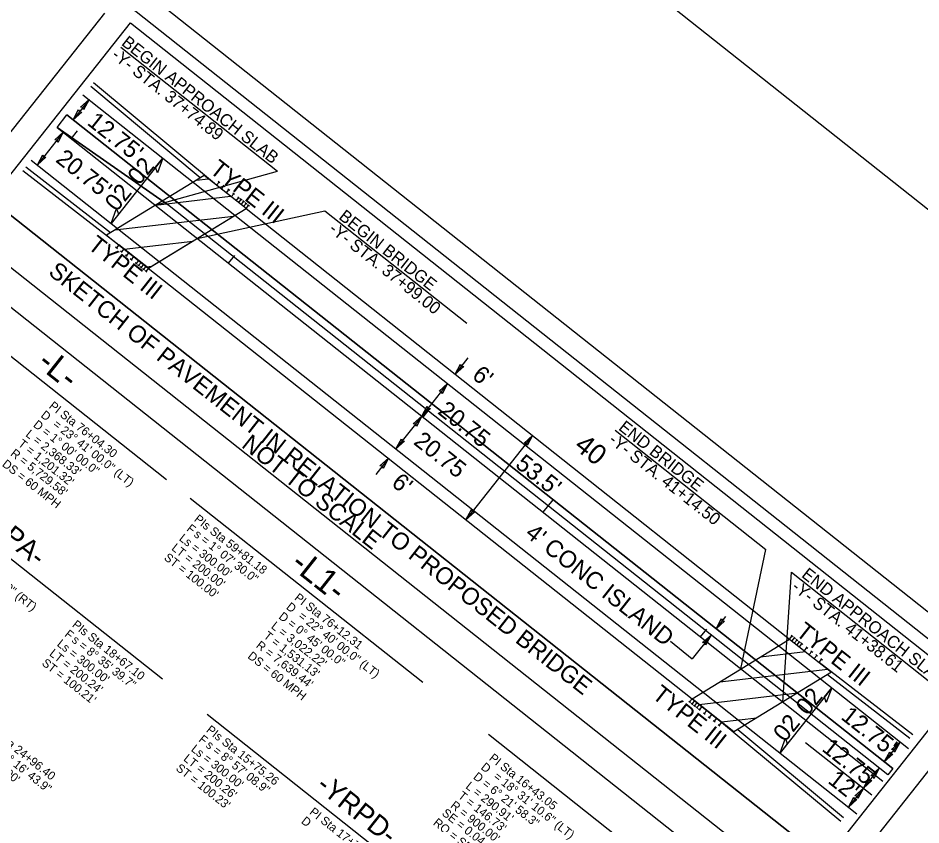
# Model space of a CAD drawing. Extents: x 1771636 to 1784627, y 798645 to 819978.
# Drawn here: x 1783314 to 1784052, y 812522 to 813181 of the extents above; entities that cross this region are included whole.
import ezdxf

# ---------------------------------------------------------------- set-up
doc = ezdxf.new("R2010")
doc.units = 0
for name, color, linetype in [('Exist Building', 7, 'Continuous'), ('Exist Hydro Pool or Reservoir', 7, 'Continuous'), ('Exist Hydro Stream Flow Arrow CELL', 7, 'Continuous'), ('Exist Hydro Stream or Body of Water', 7, 'Continuous'), ('Exist Other Culture Sign CELL', 7, 'Continuous'), ('Exist Other Culture Well CELL', 7, 'Continuous'), ('Exist Roads Change in Surface', 7, 'Continuous'), ('Exist Roads EOP Other', 7, 'Continuous'), ('Exist Roads EOT', 7, 'Continuous'), ('Exist Structure Minor Catch Basin', 7, 'Continuous'), ('Exist Structure Minor Culvert Topo', 7, 'Continuous'), ('Exist Structure Minor Drop Inlet', 7, 'Continuous'), ('Exist Structure Minor Footbridge', 7, 'Continuous'), ('Exist Structure Minor Paved Ditch or Gutter', 7, 'Continuous'), ('Exist Utilities Power Joint Use Telephone CELL', 7, 'Continuous'), ('Exist Utilities Sanitary Sewer Manhole CELL', 7, 'Continuous'), ('Exist Utilities Telephone Pole CELL', 7, 'Continuous'), ('Exist Utilities TV Satellite Dish CELL', 7, 'Continuous'), ('Exist Utilities Water Fire Hydrant CELL', 7, 'Continuous'), ('Exist Vegetation Hedge Row', 7, 'Continuous'), ('Exist Vegetation Shrub CELL', 7, 'Continuous'), ('Exist Vegetation Woods Line', 7, 'Continuous'), ('Prop CMT Guardrail Graphics', 7, 'Continuous')]:
    doc.layers.add(name, color=color, linetype=linetype)

msp = doc.modelspace()

# ---------------------------------------------------------------- linework, layer by layer
at = {"layer": 'Exist Building'}
msp.add_lwpolyline([(1783345.88, 813092.01), (1783354.04, 813102.32), (1784029, 812567.95), (1784024.92, 812562.81), (1783436.11, 813028.98)], close=True, dxfattribs=at)
at = {"layer": 'Exist Hydro Pool or Reservoir'}
for points in [[(1783365.12, 813108.46), (1783372.09, 813114.7), (1783367.62, 813106.41), (1783367.06, 813108.36)], [(1783366.08, 813104.56), (1783359.11, 813098.31), (1783363.58, 813106.6), (1783364.14, 813104.66)], [(1783343.99, 813081.78), (1783350.97, 813088.02), (1783346.49, 813079.73), (1783345.94, 813081.67)], [(1783336.81, 813067.59), (1783329.84, 813061.34), (1783334.31, 813069.63), (1783334.87, 813067.69)], [(1783678.31, 812896.58), (1783671.34, 812890.34), (1783675.81, 812898.63), (1783676.36, 812896.68)], [(1783658.26, 812876.37), (1783665.23, 812882.62), (1783660.76, 812874.33), (1783660.2, 812876.27)], [(1783651.08, 812862.19), (1783644.11, 812855.94), (1783648.58, 812864.23), (1783649.13, 812862.29)], [(1783637.13, 812849.69), (1783644.11, 812855.94), (1783639.63, 812847.65), (1783639.08, 812849.59)], [(1783629.96, 812835.51), (1783622.98, 812829.26), (1783627.46, 812837.55), (1783628.01, 812835.61)], [(1783727.7, 812833.94), (1783734.67, 812840.19), (1783730.2, 812831.9), (1783729.65, 812833.84)], [(1783609.9, 812815.3), (1783616.88, 812821.54), (1783612.4, 812813.25), (1783611.85, 812815.2)], [(1783687.18, 812777.65), (1783680.21, 812771.4), (1783684.68, 812779.69), (1783685.24, 812777.75)], [(1783891.59, 812688.5), (1783884.62, 812682.26), (1783889.09, 812690.55), (1783889.65, 812688.61)], [(1783873.58, 812670.87), (1783880.55, 812677.11), (1783876.07, 812668.82), (1783875.52, 812670.77)], [(1784028.13, 812583.54), (1784035.11, 812589.79), (1784030.63, 812581.49), (1784030.08, 812583.44)], [(1784029.1, 812579.64), (1784022.13, 812573.39), (1784026.6, 812581.68), (1784027.15, 812579.74)], [(1784011.08, 812562), (1784018.05, 812568.25), (1784013.58, 812559.96), (1784013.03, 812561.9)], [(1784012.05, 812558.1), (1784005.07, 812551.85), (1784009.55, 812560.15), (1784010.1, 812558.2)], [(1783998.1, 812545.61), (1784005.07, 812551.85), (1784000.6, 812543.56), (1784000.05, 812545.51)], [(1783999.83, 812542.67), (1783992.86, 812536.42), (1783997.33, 812544.72), (1783997.89, 812542.77)]]:
    msp.add_lwpolyline(points, close=True, dxfattribs=at)
at = {"layer": 'Exist Hydro Stream Flow Arrow CELL'}
msp.add_lwpolyline([(1784297.88, 812505.92), (1781710.58, 814554.31), (1780665.28, 813234), (1783252.58, 811185.61)], close=True, dxfattribs=at)
at = {"layer": 'Exist Other Culture Sign CELL'}
for p, q in [((1783372.09, 813114.7), (1783359.11, 813098.31)), ((1783350.97, 813088.02), (1783329.84, 813061.34)), ((1783681.84, 812903.6), (1783671.34, 812890.34)), ((1783665.23, 812882.62), (1783644.11, 812855.94)), ((1783644.11, 812855.94), (1783622.98, 812829.26)), ((1783734.67, 812840.19), (1783680.21, 812771.4)), ((1783616.88, 812821.54), (1783606.49, 812808.43)), ((1783892.47, 812692.17), (1783884.62, 812682.26)), ((1783880.55, 812677.11), (1783865.23, 812657.77)), ((1783847.29, 812671.98), (1783865.23, 812657.77)), ((1784035.11, 812589.79), (1784022.13, 812573.39)), ((1784018.05, 812568.25), (1784005.07, 812551.85)), ((1784005.07, 812551.85), (1783992.86, 812536.42))]:
    msp.add_line(p, q, dxfattribs=at)
at = {"layer": 'Exist Other Culture Well CELL'}
msp.add_lwpolyline([(1784457.99, 812708.16), (1781817.38, 814798.76), (1780451.82, 813073.93), (1783092.43, 810983.33)], close=True, dxfattribs=at)
at = {"layer": 'Exist Roads Change in Surface'}
for p, q in [((1783476.28, 813044.76), (1783375.76, 813128.45)), ((1783318.06, 813056.79), (1783396.5, 812996.02)), ((1784045.4, 812595.48), (1783968.9, 812654.75)), ((1783889.12, 812606), (1783986.49, 812524.94))]:
    msp.add_line(p, q, dxfattribs=at)
at = {"layer": 'Exist Roads EOP Other'}
for p, q in [((1783367.02, 813118.71), (1784041.98, 812584.35)), ((1783324.78, 813065.35), (1783999.73, 812530.99))]:
    msp.add_line(p, q, dxfattribs=at)
at = {"layer": 'Exist Roads EOT'}
for p, q in [((1783476.28, 813044.76), (1783478.32, 813047.34)), ((1783500.39, 813025.68), (1783476.28, 813044.76)), ((1783479.05, 813046.75), (1783477.58, 813047.92)), ((1783480.3, 813041.58), (1783482.33, 813044.15)), ((1783483.07, 813043.57), (1783481.6, 813044.74)), ((1783484.32, 813038.4), (1783486.35, 813040.97)), ((1783487.09, 813040.39), (1783485.62, 813041.56)), ((1783488.34, 813035.22), (1783490.37, 813037.79)), ((1783491.11, 813037.21), (1783489.63, 813038.38)), ((1783492.35, 813032.04), (1783494.39, 813034.61)), ((1783495.13, 813034.03), (1783493.65, 813035.19)), ((1783494.36, 813030.45), (1783496.4, 813033.02)), ((1783497.13, 813032.44), (1783495.66, 813033.6)), ((1783496.37, 813028.86), (1783498.41, 813031.43)), ((1783499.14, 813030.85), (1783497.67, 813032.01)), ((1783498.38, 813027.27), (1783500.42, 813029.84)), ((1783501.15, 813029.26), (1783499.68, 813030.42)), ((1783500.39, 813025.68), (1783502.43, 813028.25)), ((1783503.16, 813027.67), (1783501.69, 813028.83)), ((1783395.2, 812992.86), (1783393.73, 812994.03)), ((1783396.5, 812996.02), (1783394.46, 812993.45)), ((1783420.61, 812976.93), (1783396.5, 812996.02)), ((1783400.52, 812992.84), (1783398.48, 812990.27)), ((1783399.22, 812989.68), (1783397.75, 812990.85)), ((1783403.24, 812986.5), (1783401.76, 812987.67)), ((1783404.54, 812989.66), (1783402.5, 812987.08)), ((1783407.25, 812983.32), (1783405.78, 812984.49)), ((1783408.55, 812986.47), (1783406.52, 812983.9)), ((1783411.27, 812980.14), (1783409.8, 812981.3)), ((1783412.57, 812983.29), (1783410.54, 812980.72)), ((1783413.28, 812978.55), (1783411.81, 812979.71)), ((1783414.58, 812981.7), (1783412.55, 812979.13)), ((1783415.29, 812976.96), (1783413.82, 812978.12)), ((1783416.59, 812980.11), (1783414.55, 812977.54)), ((1783417.3, 812975.37), (1783415.83, 812976.53)), ((1783418.6, 812978.52), (1783416.56, 812975.95)), ((1783420.61, 812976.93), (1783418.57, 812974.36)), ((1783419.31, 812973.78), (1783417.84, 812974.94)), ((1783944.79, 812673.84), (1783946.83, 812676.41)), ((1783944.79, 812673.84), (1783968.9, 812654.75)), ((1783946.09, 812676.99), (1783947.57, 812675.83)), ((1783946.8, 812672.25), (1783948.84, 812674.82)), ((1783948.1, 812675.4), (1783949.57, 812674.24)), ((1783950.11, 812673.81), (1783951.58, 812672.64)), ((1783948.81, 812670.66), (1783950.85, 812673.23)), ((1783950.82, 812669.07), (1783952.86, 812671.64)), ((1783952.12, 812672.22), (1783953.59, 812671.05)), ((1783952.83, 812667.48), (1783954.87, 812670.05)), ((1783954.13, 812670.63), (1783955.6, 812669.46)), ((1783956.85, 812664.29), (1783958.88, 812666.87)), ((1783958.15, 812667.45), (1783959.62, 812666.28)), ((1783960.87, 812661.11), (1783962.9, 812663.68)), ((1783962.17, 812664.27), (1783963.64, 812663.1)), ((1783964.88, 812657.93), (1783966.92, 812660.5)), ((1783966.18, 812661.09), (1783967.66, 812659.92)), ((1783968.9, 812654.75), (1783970.94, 812657.32)), ((1783970.2, 812657.9), (1783971.67, 812656.74)), ((1783862.24, 812623.1), (1783863.71, 812621.94)), ((1783865.01, 812625.09), (1783862.98, 812622.52)), ((1783867.02, 812623.5), (1783864.99, 812620.93)), ((1783865.01, 812625.09), (1783889.12, 812606)), ((1783869.03, 812621.91), (1783866.99, 812619.34)), ((1783864.25, 812621.51), (1783865.72, 812620.35)), ((1783866.26, 812619.92), (1783867.73, 812618.76)), ((1783868.27, 812618.33), (1783869.74, 812617.17)), ((1783871.04, 812620.32), (1783869, 812617.75)), ((1783870.28, 812616.74), (1783871.75, 812615.57)), ((1783873.05, 812618.73), (1783871.01, 812616.16)), ((1783877.07, 812615.55), (1783875.03, 812612.98)), ((1783874.29, 812613.56), (1783875.77, 812612.39)), ((1783878.31, 812610.38), (1783879.79, 812609.21)), ((1783881.09, 812612.37), (1783879.05, 812609.8)), ((1783882.33, 812607.2), (1783883.8, 812606.03)), ((1783885.1, 812609.19), (1783883.07, 812606.61)), ((1783886.35, 812604.02), (1783887.82, 812602.85)), ((1783889.12, 812606), (1783887.09, 812603.43))]:
    msp.add_line(p, q, dxfattribs=at)
at = {"layer": 'Exist Structure Minor Catch Basin'}
for p, q in [((1783432.39, 813066.96), (1783390.14, 813013.6)), ((1783979.19, 812634.06), (1783936.94, 812580.7)), ((1783957.65, 812589.4), (1784011.94, 812546.42))]:
    msp.add_line(p, q, dxfattribs=at)
for points in [[(1783432.39, 813066.96), (1783427.97, 813054.78), (1783426.5, 813059.53)], [(1783390.14, 813013.6), (1783394.56, 813025.79), (1783396.03, 813021.04)], [(1783979.19, 812634.06), (1783974.76, 812621.87), (1783973.3, 812626.62)], [(1783936.94, 812580.7), (1783941.36, 812592.89), (1783942.82, 812588.13)]]:
    msp.add_lwpolyline(points, close=True, dxfattribs=at)
at = {"layer": 'Exist Structure Minor Drop Inlet'}
for p, q in [((1783420.61, 812976.93), (1783500.39, 813025.68)), ((1783500.39, 813025.68), (1783944.79, 812673.84)), ((1783386.36, 813004.05), (1783865.01, 812625.09)), ((1783865.01, 812625.09), (1783944.79, 812673.84))]:
    msp.add_line(p, q, dxfattribs=at)
at = {"layer": 'Exist Structure Minor Footbridge'}
for p, q in [((1784029, 812567.95), (1783354.04, 813102.32)), ((1783345.88, 813092.01), (1783436.11, 813028.98)), ((1784024.92, 812562.81), (1783436.11, 813028.98))]:
    msp.add_line(p, q, dxfattribs=at)
at = {"layer": 'Exist Utilities Power Joint Use Telephone CELL'}
for points in [[(1781915.64, 814370.28), (1784267.72, 812508.11), (1783243.53, 811214.46), (1780891.44, 813076.63)], [(1784087.57, 812602.84), (1784166.01, 812540.74), (1784096.18, 812452.53), (1784017.74, 812514.64)]]:
    msp.add_lwpolyline(points, close=True, dxfattribs=at)
at = {"layer": 'Exist Utilities Telephone Pole CELL'}
msp.add_lwpolyline([(1783384.75, 813185.41), (1782922.68, 812601.78), (1782968.4, 812565.53), (1783541.01, 812112.27), (1783700.51, 812313.71), (1783949.29, 812116.75), (1783784.11, 811908.02), (1783320.21, 811324), (1783286.6, 811356.67), (1783146.91, 811467.26), (1783125.11, 811467.64), (1783094.07, 811428.44), (1782948.68, 811547.66), (1782956.1, 811557.03), (1782756.79, 811714.83), (1782728.22, 811696.01), (1782447.03, 811920.16), (1782412.5, 811881.47), (1782072.85, 812146.5), (1782110.35, 812188.55), (1781507.48, 812669.12)], dxfattribs=at)
at = {"layer": 'Exist Utilities TV Satellite Dish CELL'}
for p, q in [((1783459.87, 813048.97), (1783469.55, 813050.09)), ((1783426.5, 813028.58), (1783487.73, 813035.7)), ((1783393.13, 813008.19), (1783490.25, 813019.48)), ((1783400.85, 812992.58), (1783456.87, 812999.09)), ((1783419.03, 812978.18), (1783423.5, 812978.7)), ((1783920.96, 812659.27), (1783957.78, 812663.55)), ((1783887.59, 812638.88), (1783975.97, 812649.16)), ((1783870.9, 812620.43), (1783951.33, 812629.78)), ((1783889.08, 812606.04), (1783917.96, 812609.39))]:
    msp.add_line(p, q, dxfattribs=at)
msp.add_lwpolyline([(1783423.59, 812978.75), (1783500.39, 813025.68), (1783466.14, 813052.8), (1783386.36, 813004.05)], dxfattribs=at)
msp.add_lwpolyline([(1783944.79, 812673.84), (1783979.05, 812646.72), (1783899.27, 812597.97), (1783865.01, 812625.09)], close=True, dxfattribs=at)
at = {"layer": 'Exist Utilities Water Fire Hydrant CELL'}
for p, q in [((1783398.1, 813157.66), (1783526.22, 813056.23)), ((1783426.25, 813028.42), (1783526.22, 813056.23)), ((1783460.5, 813001.3), (1783564.82, 813023.88)), ((1783564.82, 813023.88), (1783680.79, 812932.07)), ((1783236.89, 812961.21), (1783435.33, 812804.1)), ((1783157.37, 812858.81), (1783431.99, 812641.39)), ((1783802.23, 812844.62), (1783925.38, 812747.12)), ((1783454.72, 812789.11), (1783644.86, 812638.57)), ((1783904.9, 812649.46), (1783925.38, 812747.12)), ((1783939.16, 812622.35), (1783946.23, 812728.43)), ((1783946.23, 812728.43), (1784065.93, 812633.66)), ((1783468.73, 812612.3), (1783731.47, 812404.29)), ((1783698.69, 812595.95), (1783999.5, 812357.8))]:
    msp.add_line(p, q, dxfattribs=at)
at = {"layer": 'Exist Vegetation Hedge Row'}
for p, q in [((1783357.57, 813082.79), (1783362.66, 813089.22)), ((1783486.15, 812980.99), (1783491.24, 812987.42)), ((1783645.15, 812855.11), (1783650.24, 812861.54)), ((1783871.9, 812675.6), (1783876.99, 812682.03))]:
    msp.add_line(p, q, dxfattribs=at)
at = {"layer": 'Exist Vegetation Shrub CELL'}
for p, q in [((1783462.97, 813050.86), (1783373.42, 813125.42)), ((1783320.4, 813059.82), (1783389.72, 813006.11)), ((1784043.05, 812592.46), (1783975.68, 812644.66)), ((1783902.43, 812599.91), (1783988.94, 812527.88))]:
    msp.add_line(p, q, dxfattribs=at)
at = {"layer": 'Exist Vegetation Woods Line'}
msp.add_line((1783345.9, 813092.03), (1784020.85, 812557.67), dxfattribs=at)
for points in [[(1783405.84, 813177.35), (1784088.01, 812637.27), (1783973.7, 812492.9), (1783291.54, 813032.98)], [(1783291.54, 813032.98), (1783973.7, 812492.9), (1783952.93, 812466.66), (1783270.77, 813006.74)], [(1783243.56, 812995.92), (1784039.66, 812365.64), (1783883.72, 812168.66), (1783700.51, 812313.71), (1783541.01, 812112.27), (1782928.12, 812597.5)]]:
    msp.add_lwpolyline(points, close=True, dxfattribs=at)
at = {"layer": 'Prop CMT Guardrail Graphics'}
msp.add_line((1783743.31, 812777.4), (1783751.46, 812787.68), dxfattribs=at)

# ---------------------------------------------------------------- texts
at = {"layer": 'Exist Hydro Stream or Body of Water'}
for rotation, p in [(50.27967, (1783413.02, 813044.12)), (50.66077, (1783394.58, 813022.47)), (50.27967, (1783959.33, 812610.6)), (50.66077, (1783940.89, 812588.94))]:
    msp.add_text('02', height=14, rotation=rotation, dxfattribs=at).set_placement(p)
at = {"layer": 'Exist Roads EOT'}
for p in [(1783469.8, 813055.72), (1783370.17, 812993.73), (1783948.9, 812677.68), (1783831.48, 812626.34)]:
    msp.add_text('TYPE III', height=14, rotation=321.65959, dxfattribs=at).set_placement(p)
at = {"layer": 'Exist Structure Minor Culvert Topo'}
msp.add_text('40', height=16.4, rotation=321.63093, dxfattribs=at).set_placement((1783767.78, 812829.89))
at = {"layer": 'Exist Structure Minor Paved Ditch or Gutter'}
for s, rotation, p in [("12.75'", 321.63093, (1783369.76, 813094.79)), ("20.75'", 321.63093, (1783344.01, 813064.46)), ('SKETCH OF PAVEMENT IN RELATION TO PROPOSED BRIDGE', 321.78663, (1783337.96, 812972.3)), ("6'", 321.63093, (1783684.3, 812887.63)), ('20.75', 321.63093, (1783656.29, 812858.59)), ('NOT TO SCALE', 321.78663, (1783495.95, 812831.13)), ('20.75', 321.63093, (1783636.56, 812833.67)), ("53.5'", 321.63093, (1783719.68, 812815.02)), ("6'", 321.63093, (1783618.46, 812799.76)), ("4' CONC ISLAND", 321.63093, (1783727.74, 812758.46)), ("12.75'", 321.63093, (1783985.94, 812609.02)), ('12.75', 321.63093, (1783970.35, 812583.05)), ("12'", 321.63093, (1783975.23, 812556.83))]:
    msp.add_text(s, height=14, rotation=rotation, dxfattribs=at).set_placement(p)
at = {"layer": 'Exist Utilities Power Joint Use Telephone CELL'}
msp.add_text('TO PLOT 34"(HALF SIZE)', height=75, rotation=321.63093, dxfattribs=at).set_placement((1783522.91, 813685.26))
at = {"layer": 'Exist Utilities Sanitary Sewer Manhole CELL'}
for s, rotation, p in [('PI Sta 76+04.30', 321.71881, (1783338.8, 812863.2)), ('D', 321.71881, (1783332.08, 812855.77)), ('D = 1%%d 00\' 00.0"', 321.71881, (1783325.88, 812847.92)), ('= 23%%d 41\' 00.0" (LT)', 321.71881, (1783341.89, 812848.18)), ("L = 2,368.33'", 321.71881, (1783319.69, 812840.07)), ("T = 1,201.32'", 321.71881, (1783313.49, 812832.22)), ("R = 5,729.58'", 321.71881, (1783307.3, 812824.37)), ('DS = 60 MPH', 321.71881, (1783300.44, 812815.71)), ('PIs Sta 59+81.18', 321.94486, (1783457.45, 812770.74)), ('F', 321.94486, (1783451.28, 812762.87)), ("Ls = 300.00'", 321.94486, (1783445.12, 812754.99)), ('s = 1%%d 07\' 30.0"', 321.94486, (1783457.2, 812758.23)), ('= 26%%d 45\' 02.9" (RT)', 321.62433, (1783261.16, 812747.4)), ("LT = 200.00'", 321.94486, (1783438.95, 812747.12)), ("ST = 100.00'", 321.94486, (1783432.79, 812739.24)), ('PI Sta 76+12.31', 321.94486, (1783539.37, 812706.42)), ('D', 321.94486, (1783532.67, 812698.96)), ('D = 0%%d 45\' 00.0"', 321.94486, (1783526.51, 812691.08)), ('PIs Sta 18+67.10', 321.62433, (1783357.72, 812684.44)), ('= 22%%d 40\' 00.0" (LT)', 321.94486, (1783542.52, 812691.4)), ('F', 321.62433, (1783351.51, 812676.6)), ("L = 3,022.22'", 321.94486, (1783520.34, 812683.21)), ("Ls = 300.00'", 321.62433, (1783345.31, 812668.76)), ('s = 8%%d 35\' 39.7"', 321.62433, (1783357.4, 812671.93)), ("T = 1,531.13'", 321.94486, (1783514.18, 812675.34)), ("R = 7,639.44'", 321.94486, (1783508.02, 812667.46)), ("LT = 200.24'", 321.62433, (1783339.1, 812660.92)), ('DS = 60 MPH', 321.71881, (1783501.16, 812658.8)), ("ST = 100.21'", 321.62433, (1783332.89, 812653.08)), ('PIs Sta 24+96.40', 321.62433, (1783284.63, 812602.66)), ('PIs Sta 15+75.26', 321.63086, (1783467.32, 812598.49)), ('s = 15%%d 16\' 43.9"', 321.62433, (1783284.31, 812590.16)), ('F', 321.63086, (1783461.11, 812590.65)), ("Ls = 200.00'", 321.62433, (1783272.21, 812586.99)), ("Ls = 300.00'", 321.63086, (1783454.91, 812582.81)), ('s = 8%%d 57\' 08.9"', 321.63086, (1783467, 812585.98)), ("LT = 200.26'", 321.63086, (1783448.7, 812574.97)), ('PI Sta 16+43.05', 321.58299, (1783698.54, 812575.45)), ("ST = 100.23'", 321.63086, (1783442.49, 812567.13)), ('D', 321.58299, (1783691.8, 812568.04)), ('D = 6%%d 21\' 58.3"', 321.58299, (1783685.58, 812560.2)), ('= 18%%d 31\' 10.6" (LT)', 321.58299, (1783702.05, 812560.28)), ("L = 290.91'", 321.58299, (1783679.37, 812552.37)), ("T = 146.73'", 321.58299, (1783673.16, 812544.53)), ("R = 900.00'", 321.58299, (1783666.94, 812536.7)), ('PI Sta 17+78.72', 321.63086, (1783551.68, 812531.36)), ('SE = 0.04', 321.62433, (1783659.99, 812530.48)), ('D', 321.63086, (1783544.94, 812523.94)), ('RO = SEE PLANS', 321.62433, (1783652.81, 812522.56))]:
    msp.add_text(s, height=7, rotation=rotation, dxfattribs=at).set_placement(p)
at = {"layer": 'Exist Utilities Water Fire Hydrant CELL'}
for s, height, rotation, p in [('BEGIN APPROACH SLAB', 10, 321.65959, (1783397.91, 813159.86)), ('-Y- STA. 37+74.89', 10, 321.65959, (1783389.78, 813149.58)), ('BEGIN BRIDGE', 10, 321.65959, (1783575.52, 813017.76)), ('-Y- STA. 37+99.00', 10, 321.65959, (1783567.39, 813007.48)), ('-L-', 20, 321.63093, (1783328.53, 812897.28)), ('END BRIDGE', 10, 321.65959, (1783804.24, 812845.39)), ('-Y- STA. 41+14.50', 10, 321.65959, (1783796.11, 812835.11)), ('-YRPA-', 16.4, 321.63093, (1783270.58, 812778.66)), ('-L1-', 20, 321.63093, (1783535.63, 812732.89)), ('END APPROACH SLAB', 10, 321.65959, (1783953.83, 812725.1)), ('-Y- STA. 41+38.61', 10, 321.65959, (1783945.7, 812714.82)), ('-YRPD-', 16.4, 321.63093, (1783556.82, 812552.03))]:
    msp.add_text(s, height=height, rotation=rotation, dxfattribs=at).set_placement(p)

doc.saveas('drawing.dxf')
